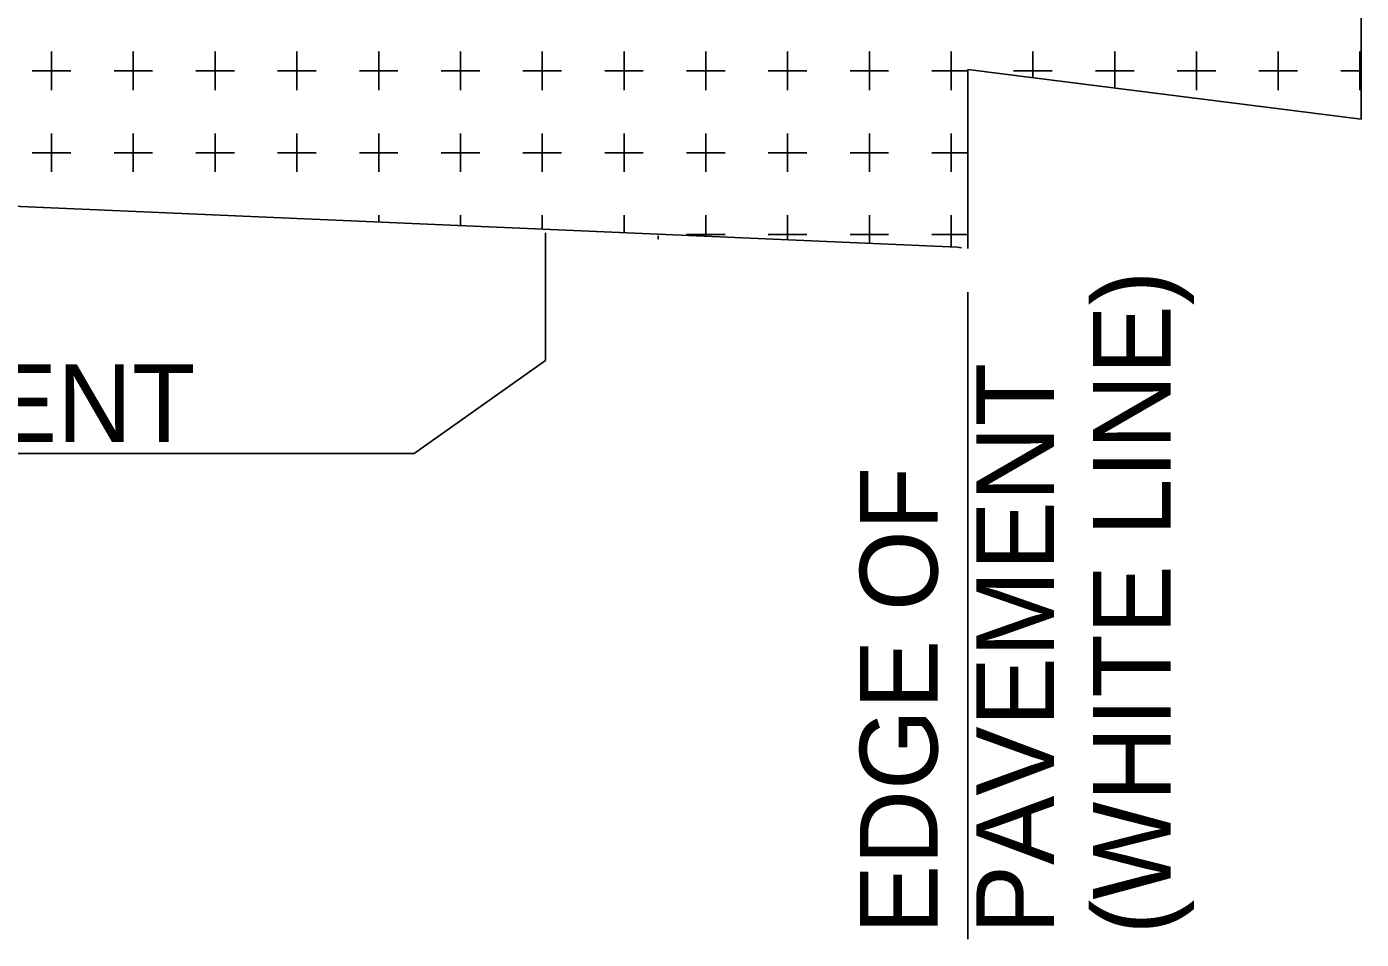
# Model space of a CAD drawing. Extents: x 0 to 34, y 0 to 22.
# Drawn here: x 19.716 to 22.122, y 10.548 to 12.193 of the extents above; entities that cross this region are included whole.
import ezdxf

# ---------------------------------------------------------------- set-up
doc = ezdxf.new("R2010")
doc.units = 0
doc.layers.add('Default', color=7, linetype='Continuous')

msp = doc.modelspace()

# ---------------------------------------------------------------- linework, layer by layer
at = {"layer": 'Default'}
for p, q in [((22.122, 12.2553), (22.122, 12.0265)), ((19.7611, 12.1135), (19.7611, 12.1483)), ((19.9085, 12.0788), (19.9085, 12.1483)), ((20.056, 12.1135), (20.056, 12.1483)), ((20.2033, 12.0788), (20.2033, 12.1483)), ((20.3508, 12.1135), (20.3508, 12.1483)), ((20.4981, 12.0788), (20.4981, 12.1483)), ((20.6455, 12.1135), (20.6455, 12.1483)), ((20.793, 12.0788), (20.793, 12.1483)), ((20.9405, 12.1135), (20.9405, 12.1483)), ((21.0878, 12.0788), (21.0878, 12.1483)), ((21.2353, 12.1135), (21.2353, 12.1483)), ((21.3826, 12.0788), (21.3826, 12.1483)), ((21.5301, 12.1135), (21.5301, 12.1483)), ((21.6775, 12.0826), (21.6775, 12.1483)), ((21.8248, 12.1135), (21.8248, 12.1483)), ((21.9723, 12.0788), (21.9723, 12.1483)), ((22.1196, 12.1135), (22.1196, 12.1483)), ((19.7263, 12.1135), (19.7611, 12.1135)), ((19.7611, 12.0788), (19.7611, 12.1135)), ((19.7611, 12.1135), (19.7958, 12.1135)), ((19.8738, 12.1135), (19.9433, 12.1135)), ((20.0211, 12.1135), (20.056, 12.1135)), ((20.056, 12.0788), (20.056, 12.1135)), ((20.056, 12.1135), (20.0906, 12.1135)), ((20.1686, 12.1135), (20.2381, 12.1135)), ((20.316, 12.1135), (20.3508, 12.1135)), ((20.3508, 12.0788), (20.3508, 12.1135)), ((20.3508, 12.1135), (20.3855, 12.1135)), ((20.4633, 12.1135), (20.5328, 12.1135)), ((20.6108, 12.1135), (20.6455, 12.1135)), ((20.6455, 12.0788), (20.6455, 12.1135)), ((20.6455, 12.1135), (20.6803, 12.1135)), ((20.7583, 12.1135), (20.8276, 12.1135)), ((20.9056, 12.1135), (20.9405, 12.1135)), ((20.9405, 12.0788), (20.9405, 12.1135)), ((20.9405, 12.1135), (20.9751, 12.1135)), ((21.0531, 12.1135), (21.1226, 12.1135)), ((21.2005, 12.1135), (21.2353, 12.1135)), ((21.2353, 12.0788), (21.2353, 12.1135)), ((21.2353, 12.1135), (21.27, 12.1135)), ((21.348, 12.1135), (21.4125, 12.1135)), ((21.4125, 12.1163), (21.4125, 11.7935)), ((21.4953, 12.1135), (21.5301, 12.1135)), ((21.5301, 12.1015), (21.5301, 12.1135)), ((21.5301, 12.1135), (21.5648, 12.1135)), ((21.6428, 12.1135), (21.7123, 12.1135)), ((21.7901, 12.1135), (21.8248, 12.1135)), ((21.8248, 12.0788), (21.8248, 12.1135)), ((21.8248, 12.1135), (21.8596, 12.1135)), ((21.9375, 12.1135), (22.007, 12.1135)), ((22.085, 12.1135), (22.1196, 12.1135)), ((22.1196, 12.0788), (22.1196, 12.1135)), ((22.1196, 12.1135), (22.122, 12.1135)), ((19.7611, 11.9313), (19.7611, 12.0008)), ((19.9085, 11.9661), (19.9085, 12.0008)), ((20.056, 11.9313), (20.056, 12.0008)), ((20.2033, 11.9661), (20.2033, 12.0008)), ((20.3508, 11.9313), (20.3508, 12.0008)), ((20.4981, 11.9661), (20.4981, 12.0008)), ((20.6455, 11.9313), (20.6455, 12.0008)), ((20.793, 11.9661), (20.793, 12.0008)), ((20.9405, 11.9313), (20.9405, 12.0008)), ((21.0878, 11.9661), (21.0878, 12.0008)), ((21.2353, 11.9313), (21.2353, 12.0008)), ((21.3826, 11.9661), (21.3826, 12.0008)), ((19.7263, 11.9661), (19.7958, 11.9661)), ((19.8738, 11.9661), (19.9085, 11.9661)), ((19.9085, 11.9313), (19.9085, 11.9661)), ((19.9085, 11.9661), (19.9433, 11.9661)), ((20.0211, 11.9661), (20.0906, 11.9661)), ((20.1686, 11.9661), (20.2033, 11.9661)), ((20.2033, 11.9313), (20.2033, 11.9661)), ((20.2033, 11.9661), (20.2381, 11.9661)), ((20.316, 11.9661), (20.3855, 11.9661)), ((20.4633, 11.9661), (20.4981, 11.9661)), ((20.4981, 11.9313), (20.4981, 11.9661)), ((20.4981, 11.9661), (20.5328, 11.9661)), ((20.6108, 11.9661), (20.6803, 11.9661)), ((20.7583, 11.9661), (20.793, 11.9661)), ((20.793, 11.9313), (20.793, 11.9661)), ((20.793, 11.9661), (20.8276, 11.9661)), ((20.9056, 11.9661), (20.9751, 11.9661)), ((21.0531, 11.9661), (21.0878, 11.9661)), ((21.0878, 11.9313), (21.0878, 11.9661)), ((21.0878, 11.9661), (21.1226, 11.9661)), ((21.2005, 11.9661), (21.27, 11.9661)), ((21.348, 11.9661), (21.3826, 11.9661)), ((21.3826, 11.9313), (21.3826, 11.9661)), ((21.3826, 11.9661), (21.4125, 11.9661)), ((20.3508, 11.841), (20.3508, 11.8535)), ((20.4981, 11.8346), (20.4981, 11.8535)), ((20.6455, 11.8283), (20.6455, 11.8535)), ((20.793, 11.8218), (20.793, 11.8535)), ((20.9405, 11.8186), (20.9405, 11.8535)), ((21.0878, 11.8091), (21.0878, 11.8535)), ((21.2353, 11.8186), (21.2353, 11.8535)), ((21.3826, 11.7963), (21.3826, 11.8535)), ((20.6517, 11.8217), (20.6517, 11.5914)), ((20.8543, 11.8105), (20.8543, 11.8165)), ((20.9056, 11.8186), (20.9405, 11.8186)), ((20.9405, 11.8155), (20.9405, 11.8186)), ((20.9405, 11.8186), (20.9751, 11.8186)), ((21.0531, 11.8186), (21.1226, 11.8186)), ((21.2005, 11.8186), (21.2353, 11.8186)), ((21.2353, 11.8026), (21.2353, 11.8186)), ((21.2353, 11.8186), (21.27, 11.8186)), ((21.348, 11.8186), (21.4125, 11.8186)), ((21.4125, 11.7149), (21.4125, 10.5482)), ((20.415, 11.4239), (20.6517, 11.5914)), ((18.0449, 11.4239), (20.415, 11.4239))]:
    msp.add_line(p, q, dxfattribs=at)
for points in [[(21.4125, 12.1163), (22.122, 12.0265)], [(19.04, 11.8978), (21.394, 11.7958), (21.4015, 11.7948)]]:
    msp.add_lwpolyline(points, dxfattribs=at)

# ---------------------------------------------------------------- texts
for s, p in [('(WHITE LINE)', (21.7781, 10.5573)), ('PAVEMENT', (21.5681, 10.5573)), ('EDGE OF', (21.3581, 10.5573))]:
    msp.add_text(s, height=0.14, rotation=90, dxfattribs=at).set_placement(p)
msp.add_text('SAW CUT PAVEMENT', height=0.14, dxfattribs=at).set_placement((18.0755, 11.4447))

doc.saveas('drawing.dxf')
